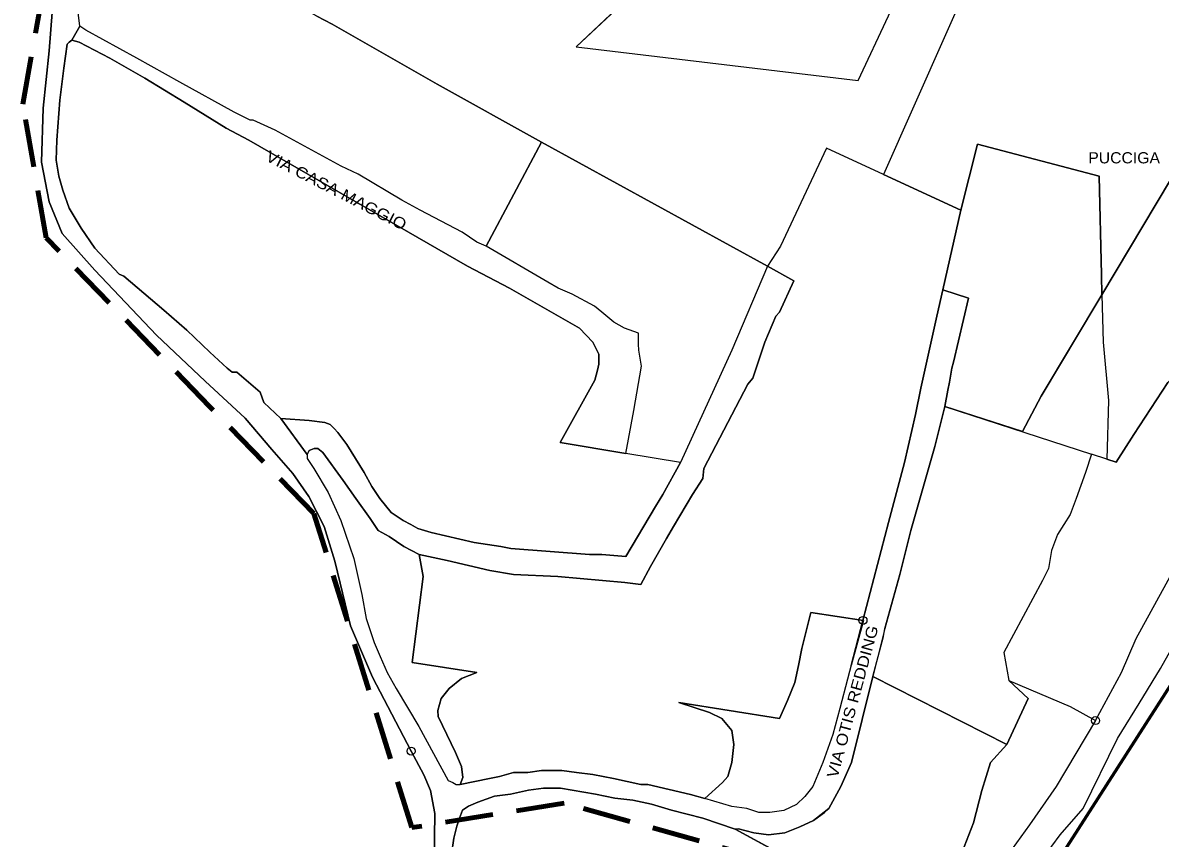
# Model space of a CAD drawing. Extents: x 654952 to 658955, y 890426 to 894481.
# Drawn here: x 657691.5 to 657975.8, y 892673.6 to 892877.3 of the extents above; entities that cross this region are included whole.
import ezdxf

# ---------------------------------------------------------------- set-up
doc = ezdxf.new("R2010")
doc.units = 0
doc.header["$LTSCALE"] = 4
doc.header["$PDMODE"] = 32
doc.header["$PDSIZE"] = 2
doc.linetypes.add('MEDIUM_DASHED', pattern=[4.5, 3, -1.5])
for name, color, linetype, lineweight in [('11', 7, 'Continuous', 25), ('13', 7, 'Continuous', 25), ('14', 7, 'Continuous', 25), ('19', 7, 'Continuous', 25), ('20', 7, 'Continuous', 25), ('29', 7, 'Continuous', 25), ('35', 7, 'Continuous', 25), ('40', 7, 'Continuous', 60), ('43', 7, 'Continuous', 25), ('5', 7, 'Continuous', 25), ('55', 7, 'Continuous', 25), ('7', 7, 'MEDIUM_DASHED', 100), ('9', 7, 'Continuous', 25)]:
    doc.layers.add(name, color=color, linetype=linetype, lineweight=lineweight)
doc.layers.add('58', color=7, linetype='Continuous')

msp = doc.modelspace()

# ---------------------------------------------------------------- linework, layer by layer
at = {"layer": '11'}
for points in [[(657841.87, 892800.94), (657839.25, 892802.44), (657836.25, 892804.94), (657834.37, 892806.44), (657828.87, 892809.44), (657825.37, 892810.94), (657822.75, 892812.44), (657807.37, 892821.44), (657821.13, 892847.44), (657877.63, 892816.44)], [(657877.63, 892816.44), (657868.75, 892795.44), (657855.87, 892767.44), (657842.27, 892769.7)], [(657842.27, 892769.7), (657844.25, 892780.44), (657846.13, 892791.44), (657845.5, 892795.44), (657845.37, 892796.94), (657845.37, 892799.75), (657841.87, 892800.94)]]:
    msp.add_lwpolyline(points, dxfattribs=at)
msp.add_lwpolyline([(657942.75, 892708.44), (657937.5, 892696.94), (657904, 892713.94), (657906.63, 892723.94), (657907, 892725.94), (657910.75, 892739.44), (657913.5, 892750.44), (657919.5, 892771.44), (657922, 892781.44), (657958.61, 892769.49), (657957.13, 892764.94), (657954.75, 892758.44), (657953.25, 892754.44), (657950.13, 892749.44), (657948.63, 892745.44), (657947.87, 892740.94), (657946.37, 892737.94), (657936.75, 892719.94), (657938, 892712.94)], close=True, dxfattribs=at)
at = {"layer": '13'}
for points in [[(657877, 892899.44), (657873, 892895.44), (657868.63, 892892.94), (657865, 892891.44), (657861.63, 892890.44), (657857.5, 892890.44), (657853.75, 892890.94), (657851.25, 892891.44), (657829.8, 892871.25)], [(657829.8, 892871.25), (657900.29, 892862.8), (657915.5, 892895.2), (657930.01, 892892.15), (657932.13, 892896.94)]]:
    msp.add_lwpolyline(points, dxfattribs=at)
at = {"layer": '14'}
msp.add_line((657959.63, 892702.94), (657949.78, 892686.5), dxfattribs=at)
for points in [[(657790.63, 892744.44), (657786.75, 892746.44), (657783.12, 892748.94), (657780.37, 892750.44), (657778.37, 892753.44), (657774.75, 892758.44), (657771.63, 892762.94), (657766.5, 892769.94), (657765.25, 892770.94), (657764.37, 892770.94), (657763.13, 892770.44), (657762.63, 892769.44), (657762.63, 892768.44), (657764.25, 892765.94), (657767.87, 892759.94), (657771, 892752.94), (657774.25, 892743.44), (657776.25, 892734.44), (657777.37, 892728.44)], [(657788.87, 892717.44), (657791.63, 892738.94), (657790.63, 892744.44)], [(657777.37, 892728.44), (657779.37, 892722.44), (657780.87, 892718.94), (657782.63, 892714.94), (657784.87, 892710.94), (657790.5, 892701.44), (657797.87, 892687.94)], [(657797.87, 892687.94), (657799, 892687.44), (657799.87, 892686.94), (657800.87, 892686.94), (657801.5, 892688.69), (657801.13, 892691.44), (657799.63, 892694.94), (657795.37, 892703.94), (657795.25, 892705.44), (657796.13, 892708.44), (657798.13, 892710.94), (657801.13, 892713.44), (657805, 892714.94), (657788.87, 892717.44)], [(657925.63, 892668.44), (657929.13, 892677.44), (657931.25, 892685.44), (657933.37, 892692.44), (657937.5, 892696.94), (657942.75, 892708.44), (657938, 892712.94), (657953.25, 892706.44), (657959.63, 892702.94)], [(657949.78, 892686.5), (657943.13, 892676.94), (657937.75, 892669.44)]]:
    msp.add_lwpolyline(points, dxfattribs=at)
msp.add_lwpolyline([(657901.51, 892727.96), (657895.75, 892705.94), (657894, 892699.44), (657891.5, 892692.44), (657889, 892686.44), (657887, 892683.94), (657884.87, 892681.94), (657881.75, 892680.44), (657878.25, 892679.94), (657875.5, 892679.94), (657872.5, 892680.94), (657868.75, 892681.44), (657862, 892683.44), (657866.37, 892687.44), (657867.75, 892688.94), (657868.75, 892692.44), (657869, 892694.69), (657869.25, 892696.94), (657868.75, 892700.44), (657866.25, 892703.44), (657863.13, 892704.94), (657855.5, 892707.44), (657880.63, 892703.44), (657882.63, 892707.94), (657884.5, 892712.44), (657885.37, 892716.69), (657886.25, 892720.94), (657888.5, 892729.94), (657901.63, 892727.94), (657898.56, 892716.69)], close=True, dxfattribs=at)
msp.add_point((657959.63, 892702.94), dxfattribs=at)
at = {"layer": '19'}
for points in [[(657766.88, 892906.77), (657806.53, 892884.39), (657817.83, 892904.16), (657824.38, 892900.44), (657823, 892897.94), (657844.88, 892885.44), (657829.8, 892871.25), (657900.29, 892862.8), (657915.5, 892895.2), (657930.01, 892892.15), (657906.64, 892839.36), (657892.37, 892845.94), (657880.87, 892821.44), (657877.63, 892816.44), (657821.13, 892847.44)], [(657821.13, 892847.44), (657795.13, 892861.94), (657768.87, 892876.94), (657765, 892878.94), (657762.37, 892880.44)]]:
    msp.add_lwpolyline(points, dxfattribs=at)
at = {"layer": '20'}
for points in [[(658024.17, 892920.51), (658017.25, 892929.44), (658008, 892941.44), (657998, 892954.44), (657994.29, 892959.11), (657983.75, 892956.29), (657967.25, 892976.32), (657932.13, 892896.94), (657930.01, 892892.15), (657906.64, 892839.36), (657926, 892830.44), (657930.13, 892846.94), (657960.5, 892838.94), (657961.09, 892814.26), (657961.21, 892809.33)], [(658024.17, 892920.51), (658004.83, 892883.1), (657992.56, 892863.36), (657978.36, 892837.99), (657961.21, 892809.33), (657961.5, 892797.44), (657962.87, 892782.94), (657962.48, 892768.22), (657964.75, 892767.48), (657969.21, 892774.37), (657977.66, 892787.42), (657998.02, 892808.54)], [(657961.21, 892809.33), (657978.36, 892837.99), (657992.56, 892863.36), (658004.83, 892883.1), (658024.17, 892920.51)]]:
    msp.add_lwpolyline(points, dxfattribs=at)
at = {"layer": '29'}
msp.add_lwpolyline([(657956, 892639.44), (657953.37, 892639.94), (657950.75, 892640.94), (657948.5, 892641.94), (657945.87, 892644.44), (657937.08, 892655.43), (657938.63, 892657.44), (657944.5, 892665.94), (657950.75, 892674.44), (657956.5, 892680.94), (657965.13, 892698.44), (657970.5, 892707.19), (657975.87, 892715.94)], dxfattribs=at)
at = {"layer": '35'}
for points in [[(657788.56, 892695.31), (657778.95, 892713.75), (657773.39, 892726.62), (657769.54, 892742.76), (657766.86, 892751.41), (657763.02, 892758.91), (657758.98, 892764.67), (657753.8, 892770.63), (657747.07, 892778.5), (657737.09, 892787.73), (657724.93, 892799.24), (657709.51, 892815.44), (657701.37, 892824.63), (657698.1, 892832.5), (657696.21, 892842.44), (657696.6, 892855.94), (657698.14, 892870.21), (657698.91, 892879.86), (657703.34, 892902.8), (657707.58, 892913.6), (657713.94, 892928.26), (657718.34, 892935.28), (657726.29, 892945.65), (657738.53, 892958.42)], [(657822.32, 892547.13), (657822.16, 892548.37), (657820.79, 892565), (657819.6, 892576.8), (657818.47, 892585.29), (657816.02, 892592.12), (657812.75, 892600.19), (657809.87, 892605.19), (657806.61, 892611.14), (657802.77, 892618.64), (657799.5, 892624.21), (657796.62, 892630.93), (657793.55, 892640.73), (657792.4, 892647.27), (657793.59, 892662.1), (657794.32, 892667.8), (657794.51, 892679.74), (657793.43, 892685.48), (657791.76, 892689.35), (657788.56, 892695.31)]]:
    msp.add_lwpolyline(points, dxfattribs=at)
msp.add_point((657788.56, 892695.31), dxfattribs=at)
at = {"layer": '40'}
msp.add_lwpolyline([(658114.09, 892964.13), (658054.45, 892838.86), (657981.91, 892717.36), (657940.54, 892652.83)], dxfattribs=at)
at = {"layer": '43'}
msp.add_line((657877.78, 892671.36), (657869.57, 892675.79), dxfattribs=at)
msp.add_lwpolyline([(657869.57, 892675.79), (657861.52, 892678.55), (657853.64, 892680.55), (657848.64, 892682.05), (657844.02, 892683.05), (657839.52, 892683.55), (657834.64, 892684.55), (657825.89, 892686.05), (657821.64, 892686.05), (657817.89, 892685.55), (657813.39, 892684.55), (657809.39, 892684.05), (657805.27, 892682.55), (657802.89, 892681.55), (657801.39, 892680.55), (657800.64, 892678.55), (657800.02, 892676.55), (657799.27, 892673.55), (657798.64, 892669.55)], dxfattribs=at)
at = {"layer": '5'}
msp.add_line((657788.56, 892695.31), (657791.76, 892689.35), dxfattribs=at)
for points in [[(657716.75, 892813.94), (657715.63, 892814.44), (657709.5, 892820.94), (657706.13, 892825.94), (657703.12, 892830.94), (657701.5, 892835.44), (657700.5, 892838.94), (657699.87, 892842.94), (657700, 892847.94), (657700.75, 892857.94), (657701.75, 892865.94), (657702.63, 892871.94), (657703.13, 892872.44), (657703.75, 892872.94), (657705.82, 892876.39), (657704.63, 892885.94)], [(657698.91, 892879.86), (657698.14, 892870.21), (657696.6, 892855.94), (657696.21, 892842.44), (657698.1, 892832.5), (657701.37, 892824.63), (657709.51, 892815.44), (657724.93, 892799.24), (657737.09, 892787.73), (657747.07, 892778.5), (657753.8, 892770.63), (657758.98, 892764.67), (657763.02, 892758.91), (657766.86, 892751.41), (657769.54, 892742.76), (657773.39, 892726.62), (657778.95, 892713.75), (657788.56, 892695.31)], [(657749.13, 892852.94), (657748.37, 892852.94), (657744.37, 892854.94), (657730.75, 892862.44), (657720, 892868.44), (657707.25, 892875.44), (657705.82, 892876.39), (657703.75, 892872.94)], [(657703.75, 892872.94), (657705.63, 892872.44), (657713.25, 892868.44), (657722, 892863.44), (657731.87, 892857.44), (657742.37, 892850.94), (657748, 892847.94), (657802.63, 892816.44)], [(657841.87, 892800.94), (657839.25, 892802.44), (657836.25, 892804.94), (657834.37, 892806.44), (657828.87, 892809.44), (657825.37, 892810.94), (657822.75, 892812.44), (657807.37, 892821.44), (657805, 892822.44), (657801.37, 892824.94), (657790.87, 892830.44), (657786.25, 892832.94), (657775.37, 892839.44), (657771.13, 892841.44), (657754.63, 892850.44), (657749.13, 892852.94)], [(657877.63, 892816.44), (657868.75, 892795.44), (657855.87, 892767.44), (657851.5, 892759.44), (657849.63, 892756.44), (657842.25, 892743.94), (657836.25, 892744.44), (657833.13, 892744.44), (657813.5, 892745.94), (657811, 892746.44), (657804.37, 892747.44), (657793.63, 892749.94), (657790.25, 892750.94)], [(657802.63, 892816.44), (657813.13, 892810.94), (657830.63, 892800.94)], [(657861.5, 892763.44), (657861.75, 892765.94), (657872.75, 892786.94), (657874, 892788.44), (657877, 892797.44), (657879.75, 892803.94), (657880.63, 892804.94), (657884.23, 892812.81), (657877.63, 892816.44)], [(657745, 892789.94), (657743.87, 892789.94), (657742.63, 892790.94), (657738.25, 892794.94), (657732.5, 892800.44), (657726.75, 892805.44), (657716.75, 892813.94)], [(657889.13, 892677.94), (657893, 892680.94), (657896, 892686.44), (657898.63, 892692.44), (657904, 892713.94), (657906.63, 892723.94), (657907, 892725.94), (657910.75, 892739.44), (657913.5, 892750.44), (657919.5, 892771.44), (657922, 892781.44), (657922.75, 892785.44), (657923.13, 892787.44), (657923.75, 892790.94), (657924.13, 892792.44), (657927.87, 892808.44), (657921.49, 892810.53)], [(657921.49, 892810.53), (657920, 892803.94), (657916, 892785.94), (657914.63, 892779.44), (657911.87, 892767.44), (657907.87, 892752.44), (657901.51, 892727.96)], [(657830.63, 892800.94), (657834, 892797.44), (657835.5, 892794.44), (657835.5, 892791.94), (657835.13, 892790.44), (657834.5, 892787.94), (657825.85, 892772.43), (657842.27, 892769.7)], [(657842.27, 892769.7), (657844.25, 892780.44), (657846.13, 892791.44), (657845.5, 892795.44), (657845.37, 892796.94), (657845.37, 892799.75), (657841.87, 892800.94)], [(657756, 892778.44), (657751.75, 892782.44), (657750.87, 892784.94), (657745, 892789.94)], [(657790.25, 892750.94), (657788.5, 892751.94), (657786.63, 892752.94), (657783.63, 892754.94), (657780.75, 892758.44), (657778.75, 892761.44), (657776.87, 892764.94), (657772.5, 892771.94), (657770.25, 892774.94), (657769.37, 892775.94), (657768.37, 892776.94), (657767, 892777.44), (657763.13, 892777.94), (657756, 892778.44), (657762.63, 892769.44)], [(657764.37, 892770.94), (657763.13, 892770.44), (657762.63, 892769.44), (657756, 892778.44)], [(657762.63, 892769.44), (657763.13, 892770.44), (657764.37, 892770.94)], [(657764.37, 892770.94), (657765.25, 892770.94), (657766.5, 892769.94), (657771.63, 892762.94), (657774.75, 892758.44), (657778.37, 892753.44), (657780.37, 892750.44), (657783.12, 892748.94), (657786.75, 892746.44), (657790.63, 892744.44), (657797.63, 892742.94)], [(657790.63, 892744.44), (657786.75, 892746.44), (657783.12, 892748.94), (657780.37, 892750.44), (657778.37, 892753.44), (657774.75, 892758.44), (657771.63, 892762.94), (657766.5, 892769.94), (657765.25, 892770.94), (657764.37, 892770.94)], [(657797.63, 892742.94), (657808.25, 892740.44), (657814.13, 892739.44), (657825.25, 892738.94), (657842, 892737.44), (657846, 892736.94), (657848.37, 892741.44), (657852.37, 892748.44), (657854.13, 892751.44), (657858.87, 892759.44), (657861.5, 892763.44)], [(657824.37, 892690.44), (657821.13, 892690.44), (657817.75, 892689.94), (657814.13, 892689.94), (657810.63, 892688.94), (657808.13, 892688.44), (657800.87, 892686.94), (657801.5, 892688.69), (657801.13, 892691.44), (657799.63, 892694.94), (657795.37, 892703.94), (657795.25, 892705.44), (657796.13, 892708.44), (657798.13, 892710.94), (657801.13, 892713.44), (657805, 892714.94), (657788.87, 892717.44), (657791.63, 892738.94), (657790.63, 892744.44)], [(657901.51, 892727.96), (657901.63, 892727.94), (657888.5, 892729.94), (657886.25, 892720.94), (657885.37, 892716.69), (657884.5, 892712.44), (657882.63, 892707.94), (657880.63, 892703.44), (657855.5, 892707.44), (657863.13, 892704.94), (657866.25, 892703.44), (657868.75, 892700.44), (657869.25, 892696.94), (657869, 892694.69), (657868.75, 892692.44), (657867.75, 892688.94), (657866.37, 892687.44), (657862, 892683.44), (657858.37, 892684.44), (657847.75, 892686.94), (657846, 892686.94), (657839.13, 892688.44), (657834, 892689.44), (657829.87, 892689.94), (657826.25, 892690.44), (657824.37, 892690.44)], [(657791.76, 892689.35), (657793.43, 892685.48), (657794.51, 892679.74), (657794.32, 892667.8), (657793.59, 892662.1), (657792.4, 892647.27), (657793.55, 892640.73), (657796.62, 892630.93), (657799.5, 892624.21), (657802.77, 892618.64), (657806.61, 892611.14), (657809.87, 892605.19), (657812.75, 892600.19), (657816.02, 892592.12), (657818.47, 892585.29), (657819.6, 892576.8), (657820.79, 892565), (657822.16, 892548.37), (657822.32, 892547.13)], [(657798.64, 892669.55), (657799.27, 892673.55), (657800.02, 892676.55), (657800.64, 892678.55), (657801.39, 892680.55), (657802.89, 892681.55), (657805.27, 892682.55), (657809.39, 892684.05), (657813.39, 892684.55), (657817.89, 892685.55), (657821.64, 892686.05), (657825.89, 892686.05), (657834.64, 892684.55), (657839.52, 892683.55), (657844.02, 892683.05), (657848.64, 892682.05), (657853.64, 892680.55), (657861.52, 892678.55), (657869.57, 892675.79)], [(657877.87, 892674.44), (657882, 892674.94), (657885.75, 892676.44), (657889.13, 892677.94)], [(657869.57, 892675.79), (657870.37, 892675.94), (657874.25, 892674.94), (657877.87, 892674.44)]]:
    msp.add_lwpolyline(points, dxfattribs=at)
for p in [(657901.51, 892727.96), (657788.56, 892695.31)]:
    msp.add_point(p, dxfattribs=at)
at = {"layer": '55'}
for points in [[(657944.5, 892665.94), (657950.75, 892674.44), (657956.5, 892680.94), (657965.13, 892698.44), (657970.5, 892707.19), (657975.87, 892715.94), (657981.19, 892725.44), (657986.5, 892734.94), (658003.13, 892765.94), (658006.37, 892769.44), (658012.25, 892779.94), (658031.63, 892810.94), (658036.5, 892818.44), (658043.75, 892831.44), (658049.75, 892842.44), (658054.5, 892849.94), (658059.81, 892859.44), (658066.63, 892872.44), (658106.37, 892949.44)], [(657978.36, 892837.99), (657946.04, 892783.96), (657941.37, 892775.12), (657922, 892781.44), (657919.5, 892771.44), (657913.5, 892750.44), (657910.75, 892739.44), (657907, 892725.94), (657904, 892713.94), (657898.63, 892692.44), (657896, 892686.44), (657893, 892680.94), (657889.13, 892677.94), (657885.75, 892676.44), (657882, 892674.94), (657877.87, 892674.44), (657874.25, 892674.94), (657870.37, 892675.94), (657869.57, 892675.79), (657877.78, 892671.36)]]:
    msp.add_lwpolyline(points, dxfattribs=at)
at = {"layer": '7'}
msp.add_lwpolyline([(657877.87, 892668.02), (657826.79, 892682.33), (657788.78, 892676.2), (657764.26, 892754.7), (657738.22, 892781.43), (657697.35, 892823.55), (657691.52, 892856.93), (657700.1, 892905.18)], dxfattribs=at)
at = {"layer": '9'}
for p, q in [((657703.75, 892872.94), (657705.82, 892876.39)), ((657762.63, 892769.44), (657756, 892778.44)), ((657901.51, 892727.96), (657907.87, 892752.44))]:
    msp.add_line(p, q, dxfattribs=at)
for points in [[(657749.13, 892852.94), (657748.37, 892852.94), (657744.37, 892854.94), (657730.75, 892862.44), (657720, 892868.44), (657707.25, 892875.44), (657705.82, 892876.39), (657704.63, 892885.94)], [(657765, 892878.94), (657768.87, 892876.94), (657795.13, 892861.94), (657821.13, 892847.44), (657807.37, 892821.44), (657805, 892822.44), (657801.37, 892824.94), (657790.87, 892830.44), (657786.25, 892832.94), (657775.37, 892839.44), (657771.13, 892841.44), (657754.63, 892850.44), (657749.13, 892852.94)], [(657748, 892847.94), (657742.37, 892850.94), (657731.87, 892857.44), (657722, 892863.44), (657713.25, 892868.44), (657705.63, 892872.44), (657703.75, 892872.94), (657703.13, 892872.44), (657702.63, 892871.94), (657701.75, 892865.94), (657700.75, 892857.94), (657700, 892847.94), (657699.87, 892842.94), (657700.5, 892838.94), (657701.5, 892835.44), (657703.12, 892830.94), (657706.13, 892825.94), (657709.5, 892820.94), (657715.63, 892814.44), (657716.75, 892813.94), (657726.75, 892805.44)], [(657830.63, 892800.94), (657813.13, 892810.94), (657802.63, 892816.44), (657748, 892847.94)], [(657907.87, 892752.44), (657911.87, 892767.44), (657914.63, 892779.44), (657916, 892785.94), (657920, 892803.94), (657921.49, 892810.53), (657926, 892830.44), (657906.64, 892839.36), (657892.37, 892845.94), (657880.87, 892821.44), (657877.63, 892816.44), (657884.23, 892812.81), (657880.63, 892804.94), (657879.75, 892803.94), (657877, 892797.44), (657874, 892788.44)], [(657998.02, 892808.54), (657977.66, 892787.42), (657969.21, 892774.37), (657964.75, 892767.48), (657962.48, 892768.22), (657958.61, 892769.49), (657957.13, 892764.94), (657954.75, 892758.44), (657953.25, 892754.44), (657950.13, 892749.44), (657948.63, 892745.44), (657947.87, 892740.94), (657946.37, 892737.94), (657936.75, 892719.94), (657938, 892712.94), (657953.25, 892706.44), (657959.63, 892702.94)], [(657959.63, 892702.94), (657966.13, 892714.94), (657969.75, 892723.44), (657987.63, 892755.94), (657989.63, 892759.44), (657998.98, 892775.24), (658013.51, 892799.02), (658013.98, 892799.82), (657998.08, 892808.51), (657998.02, 892808.54)], [(657726.75, 892805.44), (657732.5, 892800.44), (657738.25, 892794.94), (657742.63, 892790.94), (657743.87, 892789.94), (657745, 892789.94), (657750.87, 892784.94)], [(657835.13, 892790.44), (657835.5, 892791.94), (657835.5, 892794.44), (657834, 892797.44), (657830.63, 892800.94)], [(657842.27, 892769.7), (657825.85, 892772.43), (657834.5, 892787.94), (657835.13, 892790.44)], [(657874, 892788.44), (657872.75, 892786.94), (657861.75, 892765.94), (657861.5, 892763.44), (657858.87, 892759.44), (657854.13, 892751.44), (657852.37, 892748.44), (657848.37, 892741.44), (657846, 892736.94), (657842, 892737.44)], [(657750.87, 892784.94), (657751.75, 892782.44), (657756, 892778.44), (657763.13, 892777.94), (657767, 892777.44), (657768.37, 892776.94), (657769.37, 892775.94), (657770.25, 892774.94), (657772.5, 892771.94), (657776.87, 892764.94), (657778.75, 892761.44), (657780.75, 892758.44), (657783.63, 892754.94), (657786.63, 892752.94), (657788.5, 892751.94), (657790.25, 892750.94), (657793.63, 892749.94), (657804.37, 892747.44), (657811, 892746.44), (657813.5, 892745.94), (657833.13, 892744.44), (657836.25, 892744.44), (657842.25, 892743.94), (657849.63, 892756.44), (657851.5, 892759.44), (657855.87, 892767.44), (657842.27, 892769.7)], [(657842, 892737.44), (657825.25, 892738.94), (657814.13, 892739.44), (657808.25, 892740.44), (657797.63, 892742.94), (657790.63, 892744.44), (657791.63, 892738.94), (657788.87, 892717.44), (657805, 892714.94), (657801.13, 892713.44), (657798.13, 892710.94), (657796.13, 892708.44), (657795.25, 892705.44), (657795.37, 892703.94), (657799.63, 892694.94), (657801.13, 892691.44), (657801.5, 892688.69), (657800.87, 892686.94), (657808.13, 892688.44)], [(657880.63, 892703.44), (657882.63, 892707.94), (657884.5, 892712.44), (657885.37, 892716.69), (657886.25, 892720.94), (657888.5, 892729.94), (657901.63, 892727.94), (657901.51, 892727.96)], [(657893, 892680.94), (657896, 892686.44), (657898.63, 892692.44), (657904, 892713.94), (657937.5, 892696.94), (657933.37, 892692.44), (657931.25, 892685.44), (657929.13, 892677.44), (657925.63, 892668.44)], [(657808.13, 892688.44), (657810.63, 892688.94), (657814.13, 892689.94), (657817.75, 892689.94), (657821.13, 892690.44), (657824.37, 892690.44), (657826.25, 892690.44), (657829.87, 892689.94), (657834, 892689.44), (657839.13, 892688.44), (657846, 892686.94), (657847.75, 892686.94), (657858.37, 892684.44), (657862, 892683.44), (657866.37, 892687.44), (657867.75, 892688.94), (657868.75, 892692.44), (657869, 892694.69), (657869.25, 892696.94), (657868.75, 892700.44), (657866.25, 892703.44), (657863.13, 892704.94), (657855.5, 892707.44), (657880.63, 892703.44)], [(657869.57, 892675.79), (657870.37, 892675.94), (657874.25, 892674.94), (657877.87, 892674.44), (657882, 892674.94), (657885.75, 892676.44), (657889.13, 892677.94), (657891.87, 892679.94), (657893, 892680.94)], [(657883.25, 892668.44), (657869.57, 892675.79)]]:
    msp.add_lwpolyline(points, dxfattribs=at)
msp.add_lwpolyline([(657941.37, 892775.12), (657946.04, 892783.96), (657961.21, 892809.33), (657961.09, 892814.26), (657960.5, 892838.94), (657930.13, 892846.94), (657926, 892830.44), (657921.49, 892810.53), (657927.87, 892808.44), (657924.13, 892792.44), (657923.75, 892790.94), (657923.13, 892787.44), (657922.75, 892785.44), (657922, 892781.44)], close=True, dxfattribs=at)
for p in [(657901.51, 892727.96), (657959.63, 892702.94)]:
    msp.add_point(p, dxfattribs=at)

# ---------------------------------------------------------------- texts
at = {"layer": '58', "width": 1.15}
for s, height, rotation, p in [('VIA CASA MAGGIO', 2.802, 332.971, (657751.98, 892842.96)), ('VIA OTIS REDDING', 2.801, 74.801, (657895.11, 892688.38))]:
    msp.add_text(s, height=height, rotation=rotation, dxfattribs=at).set_placement(p)
at = {"layer": '58', "width": 1.05}
msp.add_text('PUCCIGA', height=2.801, dxfattribs=at).set_placement((657957.82, 892842.13))

doc.saveas('drawing.dxf')
